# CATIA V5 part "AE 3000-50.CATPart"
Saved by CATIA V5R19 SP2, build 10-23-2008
Part number: AE 3000-50
Bounding box of the stored display mesh (mm): x -47.487 to 47.487, y -47.487 to 47.487, z 0 to 170
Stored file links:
  C:\Users\Bora\Desktop\3D Katı model\AE serisi\AE 3000\AE 3000-50.CATPart
  C:\Program Files\Dassault Systemes\B19\intel_a\reffiles\standard\MetricThickPitch.txt
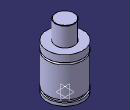
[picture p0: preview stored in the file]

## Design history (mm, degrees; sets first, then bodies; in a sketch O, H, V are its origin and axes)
Body1 (main body)
  Sketch1 on yz-plane, origin (0, 0, 0), H (0, 1, 0), V (0, 0, 1)
    point P1 (47.5, 100.5)
    point P5 (25, 169)
    point P7 (25, 169)
    point P12 (47.5, 95.5)
    point P13 (47.5, 100.5)
    point P14 (47.5, 95.5)
    line L1 (47.5, 100.5) -> (47.5, 119)
    line L2 (47.5, 0) -> (47.5, 8)
    arc A1 centre (24, 169) radius 1 from (25, 169) to (24, 170) ccw
    line L3 (25, 169) -> (25, 119)
    line L4 (43.5, 15) -> (43.5, 8)
    line L5 (47.5, 15) -> (47.5, 95.5)
    arc A2 centre (47.5, 98) radius 2.5 from (47.5, 100.5) to (47.5, 95.5) ccw
    line L6 (24, 170) -> (0, 170)
    point P15 (0, 170)
    line L7 (25, 119) -> (47.5, 119)
    line L8 (0, 0) -> (47.5, 0)
    line L9 (43.5, 15) -> (47.5, 15)
    line L10 (43.5, 8) -> (47.5, 8)
    coincidence: P15 V, P1 P13, P5 P7, P12 P14
    tangency: L6 A1
    horizontal: L7 H, L8 H, L9 H, L10 H
  Shaft1: profile Sketch1, axis Sketch1.V, angle 360
  Sketch2 on face of Shaft1 from Sketch1.L8, origin (0, 0, 0), H (1, 0, 0), V (0, -1, 0)
    point P1 (30, 0)
    distance P1 V = 30
  Hole1: placed by Sketch2, at (30, 0, 0) direction (0, 0, 1), diameter 6.647, depth 13, threaded "M8", thread diameter 8, thread depth 13, pitch 1.25
  CircPattern1: of Hole1, instances 4, angular step 90, axis from xy-plane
